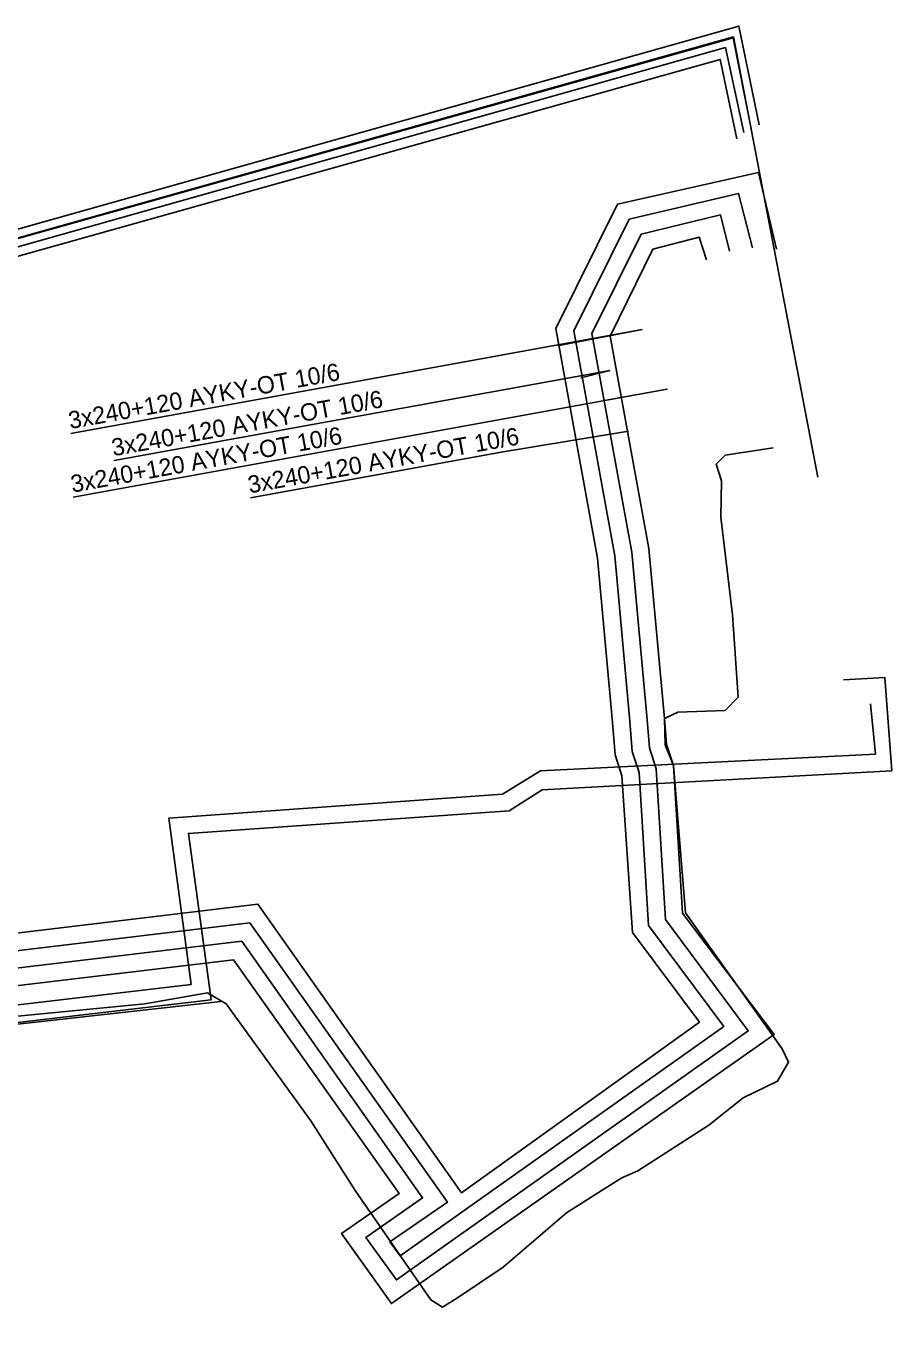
# Model space of a CAD drawing. Extents: x -744800 to -744528, y -1052473 to -1052336.
# Drawn here: x -744577.6 to -744527.7, y -1052412.6 to -1052337.4 of the extents above; entities that cross this region are included whole.
import ezdxf

# ---------------------------------------------------------------- set-up
doc = ezdxf.new("R2010")
doc.units = 0
for name, color, linetype in [('NN_KABELOVE_VEDENI_PROVOZ', 7, 'Continuous'), ('NN_KABELOVE_VEDENI_VYRAZENO', 7, 'Continuous'), ('NN_POPIS_USEKU', 7, 'Continuous'), ('TRASA_KABELU_NN', 7, 'Continuous'), ('TRASA_KABELU_NN_PROVOZ', 7, 'Continuous')]:
    doc.layers.add(name, color=color, linetype=linetype)

msp = doc.modelspace()

# ---------------------------------------------------------------- linework, layer by layer
at = {"layer": 'NN_KABELOVE_VEDENI_PROVOZ'}
for points in [[(-744633.183, -1052356.642), (-744633.521, -1052351.56), (-744626.684, -1052351.094), (-744623.911, -1052387.31), (-744623.568, -1052390.367), (-744623.165, -1052395.131), (-744564.248, -1052388.055), (-744552.516, -1052404.718), (-744538.787, -1052394.869), (-744542.655, -1052389.688), (-744543.251, -1052380.647), (-744543.648, -1052379.434), (-744543.791, -1052377.578), (-744544.659, -1052368.082), (-744547.073, -1052354.821), (-744543.518, -1052347.643), (-744535.387, -1052345.83), (-744534.333, -1052350.257)], [(-744535.725, -1052350.166), (-744536.539, -1052347.029), (-744542.833, -1052348.513), (-744546.03, -1052354.968), (-744543.667, -1052367.947), (-744542.794, -1052377.494), (-744542.66, -1052379.237), (-744542.264, -1052380.448), (-744541.729, -1052389.291), (-744537.38, -1052395.122), (-744556.054, -1052408.356), (-744556.636, -1052407.541), (-744553.323, -1052405.266), (-744564.717, -1052389.127), (-744624.074, -1052396.246), (-744624.583, -1052390.597), (-744662.551, -1052395.016)], [(-744537.048, -1052350.359), (-744537.561, -1052348.275), (-744542.149, -1052349.383), (-744544.986, -1052355.114), (-744542.689, -1052367.739), (-744541.797, -1052377.417), (-744541.672, -1052379.041), (-744541.277, -1052380.249), (-744540.75, -1052388.947), (-744535.972, -1052395.375), (-744556.265, -1052409.748), (-744558.027, -1052407.303), (-744554.757, -1052405.017), (-744565.186, -1052390.199), (-744624.983, -1052397.36), (-744625.43, -1052391.735), (-744663.451, -1052396.18)], [(-744538.381, -1052350.871), (-744538.795, -1052349.559), (-744541.464, -1052350.254), (-744543.943, -1052355.261), (-744541.71, -1052367.53), (-744540.8, -1052377.34), (-744540.684, -1052378.844), (-744540.29, -1052380.05), (-744539.771, -1052388.576), (-744534.484, -1052395.587), (-744556.551, -1052411.113), (-744559.424, -1052407.065), (-744556.106, -1052404.763), (-744565.654, -1052391.273), (-744625.892, -1052398.475), (-744626.303, -1052392.793), (-744664.403, -1052397.238)], [(-744799.958, -1052408.482), (-744800.116, -1052406.505), (-744794.132, -1052405.926), (-744768.563, -1052404.243), (-744751.319, -1052402.793), (-744733.275, -1052401.051), (-744733.48, -1052398.511), (-744731.401, -1052398.392), (-744727.771, -1052398.622), (-744714.274, -1052400.592), (-744713.445, -1052400.003), (-744705.181, -1052400.423), (-744705.583, -1052403.661), (-744687.509, -1052405.817), (-744668.651, -1052404.712), (-744627.976, -1052399.751), (-744625.876, -1052400.487), (-744566.945, -1052393.578), (-744568.26, -1052383.974), (-744549.76, -1052382.661), (-744547.856, -1052381.455), (-744527.683, -1052380.355), (-744528.085, -1052374.982), (-744530.485, -1052375.105)], [(-744701.233, -1052459.94), (-744697.975, -1052462.013), (-744701.204, -1052455.312), (-744721.631, -1052413.856), (-744727.534, -1052401.666), (-744727.626, -1052397.603), (-744714.621, -1052399.45), (-744713.238, -1052398.803), (-744704.151, -1052399.748), (-744704.544, -1052402.838), (-744687.321, -1052404.806), (-744668.44, -1052403.653), (-744628.032, -1052398.743), (-744625.696, -1052399.462), (-744568.109, -1052392.689), (-744569.387, -1052383.09), (-744550.152, -1052381.714), (-744547.961, -1052380.354), (-744528.632, -1052379.391), (-744528.92, -1052376.499)]]:
    msp.add_lwpolyline(points, dxfattribs=at)
at = {"layer": 'NN_KABELOVE_VEDENI_VYRAZENO'}
for points in [[(-744535.335, -1052343.068), (-744536.509, -1052337.369), (-744584.547, -1052350.894), (-744625.118, -1052352.025), (-744625.33, -1052349.612), (-744632.336, -1052350.014), (-744633.137, -1052338)], [(-744695.064, -1052365.586), (-744688.714, -1052365.142), (-744687.72, -1052363.83), (-744688.058, -1052357.204), (-744666.87, -1052355.829), (-744663.039, -1052357.374), (-744644.539, -1052353.754), (-744633.944, -1052353.041), (-744634.05, -1052351.136), (-744626.176, -1052350.586), (-744625.986, -1052353.084), (-744584.452, -1052351.895), (-744537.287, -1052338.607), (-744536.224, -1052343.513)], [(-744535.795, -1052343.306), (-744536.843, -1052338.052), (-744584.484, -1052351.418), (-744625.541, -1052352.533), (-744625.774, -1052350.057), (-744634.558, -1052350.692), (-744634.453, -1052352.618), (-744644.706, -1052353.278), (-744662.54, -1052356.847), (-744665.582, -1052354.733), (-744689.095, -1052356.294), (-744688.812, -1052363.65), (-744689.117, -1052364.084), (-744695.043, -1052364.655)], [(-744536.621, -1052343.878), (-744537.589, -1052339.29), (-744584.277, -1052352.387), (-744624.918, -1052353.514)]]:
    msp.add_lwpolyline(points, dxfattribs=at)
at = {"layer": 'NN_POPIS_USEKU'}
for points in [[(-744575.031, -1052360.882), (-744542.093, -1052354.886), (-744546.875, -1052355.813)], [(-744572.545, -1052362.45), (-744543.958, -1052357.246), (-744545.63, -1052357.683)], [(-744574.905, -1052364.555), (-744540.652, -1052358.323), (-744544.261, -1052358.991)], [(-744564.686, -1052364.597), (-744550.226, -1052361.965), (-744542.879, -1052360.762)]]:
    msp.add_lwpolyline(points, dxfattribs=at)
at = {"layer": 'TRASA_KABELU_NN'}
msp.add_lwpolyline([(-744628.642, -1052352.639), (-744584.523, -1052351.406), (-744536.828, -1052337.999), (-744531.954, -1052363.41)], dxfattribs=at)
at = {"layer": 'TRASA_KABELU_NN_PROVOZ'}
for points in [[(-744534.53, -1052361.72), (-744537.3, -1052362.14), (-744537.82, -1052362.65), (-744537.51, -1052363.62), (-744537.56, -1052365.72), (-744536.88, -1052371.35), (-744536.55, -1052376.1), (-744537.31, -1052376.88), (-744540.04, -1052376.98), (-744540.8, -1052377.34), (-744540.77, -1052378.86), (-744540.29, -1052380.05), (-744539.59, -1052388.56), (-744534.01, -1052396.41), (-744533.64, -1052397.17), (-744534.28, -1052398.27), (-744536.27, -1052399.23), (-744538.25, -1052400.82), (-744542.33, -1052403.46), (-744543.26, -1052403.86), (-744544.24, -1052404.47), (-744546.45, -1052405.87), (-744550.1, -1052409.02), (-744552.73, -1052410.79), (-744553.61, -1052411.32), (-744554.28, -1052410.9), (-744558.64, -1052404.58), (-744561.19, -1052400.57), (-744566.08, -1052393.81), (-744567.15, -1052393.18), (-744570.78, -1052393.81), (-744578.31, -1052394.55)], [(-744625.739, -1052400.545), (-744593.305, -1052396.676), (-744566.393, -1052393.669)]]:
    msp.add_lwpolyline(points, dxfattribs=at)

# ---------------------------------------------------------------- texts
at = {"layer": 'NN_POPIS_USEKU'}
for rotation, p in [(10.3171, (-744575.076, -1052360.636)), (10.31846, (-744572.589, -1052362.204)), (10.31161, (-744574.949, -1052364.309)), (10.31522, (-744564.73, -1052364.351))]:
    msp.add_text('3x240+120 AYKY-OT 10/6', height=1, rotation=rotation, dxfattribs=at).set_placement(p)

doc.saveas('drawing.dxf')
